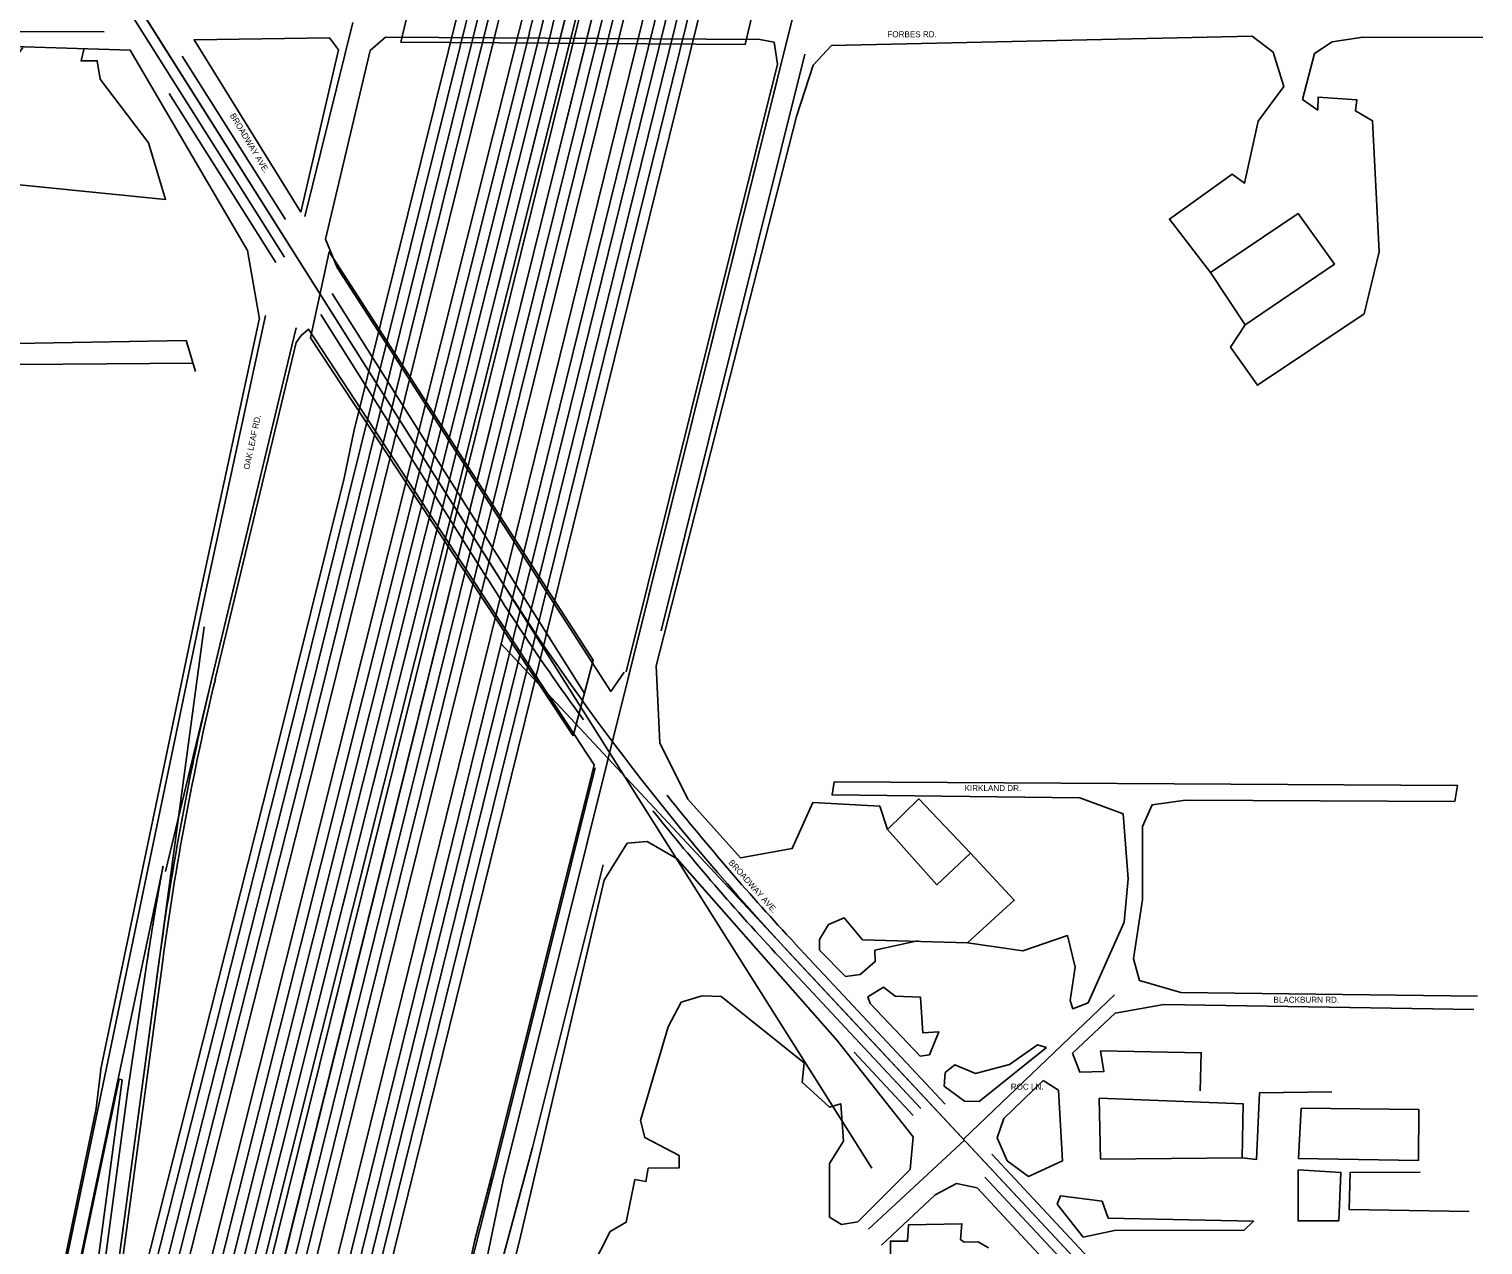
# Model space of a CAD drawing. Extents: x 227157 to 233208, y 434992 to 456232.
# Drawn here: x 228028 to 229709, y 444181 to 445587 of the extents above; entities that cross this region are included whole.
import ezdxf

# ---------------------------------------------------------------- set-up
doc = ezdxf.new("R2010")
doc.units = 0
for name, color, linetype in [('BD_X_Building', 7, 'Continuous'), ('BR_X_Slab_Object', 7, 'Continuous'), ('Default', 7, 'Continuous'), ('GE_X_Alignment', 7, 'Continuous'), ('PM_X_Edge_Line', 7, 'Continuous'), ('PM_X_Lane_Line', 7, 'Continuous'), ('PV_X_EOP', 7, 'Continuous'), ('SV_X_Text_Name', 7, 'Continuous')]:
    doc.layers.add(name, color=color, linetype=linetype)

msp = doc.modelspace()

# ---------------------------------------------------------------- linework, layer by layer
at = {"layer": 'BD_X_Building'}
for points in [[(229394.3, 445305.7), (229434.3, 445245), (229537.4, 445315.1), (229495.4, 445373.8)], [(229020.7, 444661.4), (229057, 444696.9), (229116.6, 444634), (229077.9, 444597.6)], [(229265.6, 444350.8), (229267, 444280.4), (229430.9, 444281.9), (229431.8, 444344.4)], [(229498.9, 444339.5), (229495.8, 444281.3), (229634.6, 444278.9), (229635.2, 444337.7)], [(229495.7, 444268.2), (229495.5, 444208.9), (229542.5, 444209.2), (229544.9, 444265)]]:
    msp.add_lwpolyline(points, close=True, dxfattribs=at)
at = {"layer": 'BR_X_Slab_Object'}
for points in [[(228457.7, 445571.8), (228470.5, 445625.7), (228868.7, 445623.1), (228856.1, 445569.3)], [(228657.1, 444769.9), (228680.1, 444857.3), (228375, 445329.6), (228353.3, 445229.9)]]:
    msp.add_lwpolyline(points, close=True, dxfattribs=at)
at = {"layer": 'Default'}
msp.add_open_spline([(228182.9, 444619.3), (228182.6, 444617.6), (228181.9, 444614), (228180.9, 444608.7), (228180, 444603.3), (228179, 444598), (228178.1, 444592.7), (228177.2, 444587.3), (228176.2, 444582), (228175.3, 444576.6), (228174.4, 444571.3), (228173.5, 444565.9), (228172.6, 444560.6), (228171.7, 444555.2), (228170.9, 444549.8), (228170, 444544.5), (228169.2, 444539.1), (228168.3, 444533.8), (228167.5, 444528.4), (228166.6, 444523), (228165.8, 444517.7), (228165.3, 444514.1), (228165, 444512.3)], degree=3, dxfattribs=at)
at = {"layer": 'GE_X_Alignment'}
for p, q in [((228062.6, 442805), (229317.7, 447888.8)), ((228348.7, 444751.1), (228850.5, 446773.2)), ((227958.1, 442696), (228945.6, 446675.5)), ((227973.9, 442912.3), (228887.3, 446553.8)), ((227769.3, 446224), (229002.6, 444269.9)), ((228576.1, 444256.1), (229057.6, 446188.4)), ((228185.7, 444612.8), (228336.9, 445241.5)), ((227788.2, 442806.3), (228231.6, 444933.5)), ((228012.9, 443278.3), (228230.3, 444895.8)), ((228573.2, 444877), (229685.5, 443685.5)), ((227857.2, 442809.2), (228348.7, 444751.1))]:
    msp.add_line(p, q, dxfattribs=at)
for centre, radius, start, end in [((216725.3, 448562.4), 12285.2, 345.91876, 353.32977), ((231051.2, 446525.5), 2936.3, 212.2571, 223.0314), ((231389.3, 444078.9), 3239.6, 166.4801, 172.3433)]:
    msp.add_arc(centre, radius, start, end, dxfattribs=at)
at = {"layer": 'PM_X_Edge_Line'}
for p, q in [((228568.1, 444958.3), (227769.3, 446224)), ((228361.2, 444014.4), (228765.4, 445651.6)), ((228294, 444049.5), (228690.2, 445646.1)), ((228317.3, 444043.7), (228713.5, 445640.3)), ((228325.4, 444756.9), (228546.3, 445647.1)), ((228348.7, 444751.1), (228569.6, 445641.3)), ((228396.1, 444005.7), (228800.3, 445643)), ((228576.1, 444256.1), (228913.2, 445609)), ((228606.5, 445582.2), (228232.4, 444091)), ((228346.9, 445370.3), (228402.2, 445594.6)), ((228267.3, 444082.3), (228641.4, 445573.4)), ((228759.1, 444891.3), (228925.2, 445558)), ((228313.3, 445317.1), (228189.9, 445512.6)), ((228231.6, 444933.5), (228301.4, 445255.9)), ((228239.4, 444836.2), (228336.9, 445241.5)), ((228030.5, 443969), (228231.6, 444933.5)), ((228163.7, 444117.8), (228325.4, 444756.9)), ((228186.9, 444111.9), (228348.7, 444751.1)), ((228571.1, 444285.9), (228682.5, 444733)), ((228131.1, 444373.2), (228182.9, 444619.3)), ((228610.2, 444294), (228691.7, 444620.8)), ((229685.5, 443685.5), (228904.8, 444521.7)), ((228067, 443681.1), (228178.5, 444510.5)), ((228165, 444512.3), (228141.8, 444357.4)), ((229108.4, 444303.6), (229283, 444470.3)), ((228982, 444403.9), (229050.4, 444330.7)), ((228045.6, 443965.8), (228131.1, 444373.2)), ((228141.8, 444357.4), (228051.2, 443683.3)), ((228542, 444170.2), (228571.1, 444285.9)), ((228571.7, 444150), (228610.2, 444294)), ((228998.7, 444199.4), (229109.7, 444302.3)), ((228555.4, 444155.9), (228576.1, 444256.1))]:
    msp.add_line(p, q, dxfattribs=at)
for centre, radius, start, end in [((216725.3, 448562.4), 12249.2, 345.91876, 353.32977), ((216725.3, 448562.4), 12285.2, 345.91876, 353.32977), ((231051.2, 446525.5), 2936.3, 212.2571, 223.0314), ((231389.3, 444078.9), 3239.6, 166.4801, 172.3433)]:
    msp.add_arc(centre, radius, start, end, dxfattribs=at)
at = {"layer": 'PM_X_Lane_Line'}
for p, q in [((228323.4, 445323.5), (228028.9, 445790.1)), ((228372.8, 444011.5), (228777, 445648.7)), ((228701.8, 445643.2), (228305.7, 444046.6)), ((228337.1, 444754), (228558, 445644.2)), ((228384.5, 444008.6), (228788.7, 445645.9)), ((227924.7, 445584.6), (228114.7, 445583.8)), ((228244.1, 444088.1), (228618.1, 445579.3)), ((228629.7, 445576.4), (228255.7, 444085.2)), ((228205.1, 445555.9), (228324.6, 445366.7)), ((228378.5, 445281.3), (228669.9, 444819.4)), ((228365.4, 445257.1), (228557.9, 444951.9)), ((228175.3, 444114.9), (228337.1, 444754)), ((228913.6, 444529.9), (229087.4, 444343.8)), ((229059.1, 444338.9), (228896.1, 444513.5)), ((229141.3, 444286.1), (229528.4, 443871.4)), ((229505.7, 443860.5), (229133.3, 444259.5))]:
    msp.add_line(p, q, dxfattribs=at)
for centre, radius, start, end in [((216725.3, 448562.4), 12261.2, 345.91876, 353.32977), ((216725.3, 448562.4), 12273.2, 345.91876, 353.32977), ((231051.2, 446525.5), 2948.3, 212.2571, 216.1028), ((231051.2, 446525.5), 2924.3, 218.6008, 223.0314), ((231051.2, 446525.5), 2948.3, 218.6722, 223.0314)]:
    msp.add_arc(centre, radius, start, end, dxfattribs=at)
at = {"layer": 'PV_X_EOP'}
for p, q in [((228280.4, 444052.9), (228676.6, 445649.5)), ((228347.6, 444017.7), (228751.8, 445655)), ((228403.6, 445121.9), (228534.7, 445650)), ((228328.9, 444040.8), (228725.1, 445637.4)), ((228360.3, 444748.2), (228581.3, 445638.4)), ((228407.8, 444002.9), (228812, 445640.1)), ((228220.8, 444093.9), (228594.8, 445585.1)), ((228279, 444079.3), (228653, 445570.5)), ((228422.6, 445562.3), (228370.7, 445344.3)), ((228718.4, 444843.9), (228893.5, 445546.6)), ((228225.7, 444934.7), (228294.2, 445251.3)), ((228336.9, 445224.6), (228342.5, 445232.7)), ((228209.5, 445227.1), (228220.5, 445191.3)), ((228336.9, 445224.6), (228243.3, 444835.3)), ((228392.2, 445067.6), (228403.6, 445121.9)), ((228315.7, 444759.4), (228392.2, 445067.6)), ((228110.7, 444382.9), (228225.7, 444934.7)), ((228154, 444120.3), (228315.7, 444759.4)), ((228198.6, 444109), (228360.3, 444748.2)), ((228562.4, 444259.2), (228681.3, 444736.4)), ((228942, 444522.2), (228972, 444491.4)), ((228182.5, 444510), (228106.7, 443946.3)), ((229000.8, 444460.3), (229058.4, 444399.3)), ((228043.2, 443684.3), (228135.7, 444371.9)), ((228046.6, 443965.6), (228132.1, 444372.9)), ((228105.6, 444338.8), (228111, 444383.5)), ((228131.1, 444373.2), (228135.7, 444371.9)), ((228028.6, 443969.4), (228105.6, 444338.8)), ((228543, 444185), (228562.4, 444259.2)), ((228562.3, 444258.8), (228562.4, 444259.2)), ((229510.8, 443831.9), (229124.3, 444247.2)), ((229216.7, 444228.5), (229247, 444190.3)), ((229554.7, 444222.1), (229693.2, 444219.9)), ((228537.8, 444159.9), (228543, 444185))]:
    msp.add_line(p, q, dxfattribs=at)
for points in [[(227744.7, 445578), (227773.6, 445563), (227776.7, 445488.4), (227778.9, 445253.6), (227812.4, 445212.5), (227864.9, 445197.9), (228218.3, 445200.8)], [(228209.5, 445227.1), (227880.9, 445221.1), (227825.6, 445227.3), (227807.4, 445252.2), (227803.5, 445561.5), (227826.5, 445572.7)], [(228294.6, 445251.8), (228280.4, 445330.9), (228145, 445562.5), (227826.5, 445572.7)], [(228020.6, 445565.8), (228016, 445559.1), (227956.5, 445549.2), (227959.2, 445412.9), (228185.9, 445390.2), (228166.1, 445455.4), (228110.2, 445529), (228106.9, 445550.5), (228088.1, 445550.2), (228091.1, 445563.5)], [(228422.6, 445562.3), (228440.1, 445577.6), (228872.9, 445575.2), (228889.5, 445571.9), (228893.5, 445546.6)], [(228753, 444850.8), (228915.4, 445485.9), (228934.8, 445545.3), (228956, 445568)], [(228956, 445568), (229442.3, 445578.8), (229466.6, 445560.2)], [(229514.4, 445558.9), (229534.9, 445572.4), (229570.2, 445577.9), (229709.2, 445577.3)], [(229466.6, 445560.2), (229478.8, 445520.7), (229449.4, 445480.7), (229433.4, 445408.9), (229419.2, 445419.2), (229346.7, 445367.3), (229394.3, 445305.7)], [(229434.3, 445245), (229417.4, 445219.1), (229448.5, 445175.3), (229571.8, 445257.9), (229589.2, 445329.5), (229581.7, 445481), (229561.8, 445492.5), (229563.4, 445505.3), (229518.6, 445508.5), (229518.2, 445493.5), (229500.5, 445505.6), (229514.4, 445558.9)], [(228370.7, 445344.3), (228384.2, 445311.4), (228700.6, 444821.2), (228716.3, 444843.5)], [(228681.3, 444736.4), (228351.2, 445239.9), (228342.5, 445232.7)], [(228850.5, 444628.6), (228789.6, 444696.5), (228757.2, 444761.8), (228753, 444850.8)], [(229252.9, 444461.1), (229294.5, 444554.5), (229299.1, 444604.6), (229293.3, 444679.5), (229243.2, 444698.3), (228956.6, 444701.6), (228958.9, 444716.6), (229679.7, 444712.6), (229676.7, 444694), (229365.1, 444695.5), (229326.7, 444690.1), (229315.5, 444665.2)], [(228850.5, 444628.6), (228910.5, 444639.4), (228934.4, 444692.8), (229011.7, 444688.4), (229020.7, 444661.4)], [(229315.5, 444665.2), (229315.5, 444580.6), (229305.1, 444511.9), (229311.9, 444486.8), (229359.9, 444473.1), (229702.8, 444468.9)], [(228719.6, 444645.6), (228693, 444602.8), (228594.8, 444184.3), (228521.3, 443893.9), (228494.9, 443739.1), (228462.9, 443544.8), (228445.5, 443382.8)], [(229050.4, 444306.3), (228962.4, 444417.5), (228777.6, 444627.7), (228742.6, 444647.5), (228719.6, 444645.6)], [(229116.6, 444634), (229167.2, 444579.8), (229113.3, 444530.6), (229177.2, 444521.4), (229228.7, 444538.9), (229237.5, 444502.3), (229231.8, 444463.9), (229234.8, 444454.2), (229252.9, 444461.1)], [(229113.3, 444530.6), (228991.9, 444534.1), (228970.4, 444559.4), (228952.3, 444551.7), (228942, 444534.5), (228942, 444522.2)], [(228972, 444491.4), (228988.9, 444493.9), (229006.4, 444508.9), (229006.1, 444522), (229055.5, 444532.7)], [(229058.4, 444399.3), (229069.1, 444400.9), (229080.1, 444427.5), (229061.6, 444426.4), (229058.9, 444467.5), (229029.6, 444468.8), (229016, 444479.2), (228998, 444467.9), (229000.8, 444460.3)], [(228953.4, 444213.1), (228953.7, 444275.3), (228969.9, 444301.3), (228966.6, 444344.5), (228953.4, 444340.5), (228921.9, 444369.2), (228924.3, 444391.9), (228828.4, 444468.3), (228806.3, 444469.2), (228782.1, 444461.7), (228767.2, 444433.5), (228734.9, 444324.9), (228739.9, 444305.3), (228779.9, 444284.5), (228779.6, 444270.2), (228743.8, 444269.9), (228741.2, 444254.4), (228728.5, 444256.7), (228718.5, 444207.4), (228699.8, 444196.6), (228668.1, 444133.8)], [(229698.8, 444453.3), (229340.1, 444459), (229283.8, 444449.2), (229234.7, 444402.9)], [(229204.6, 444409.4), (229194.2, 444412.7), (229161.9, 444389.7), (229122.3, 444379.5), (229098.5, 444389.4), (229087.3, 444380.4), (229086.1, 444364.6)], [(229086.1, 444364.6), (229109.6, 444347.4), (229126.7, 444346.9), (229204.6, 444409.4)], [(229234.7, 444402.9), (229243.1, 444380.8), (229271, 444381.6), (229267.1, 444405.5), (229383.4, 444403.4), (229382.4, 444359.2)], [(229200.5, 444371.5), (229155.2, 444327.4), (229147.5, 444305.1), (229159, 444278.5), (229183.8, 444260.3)], [(229200.5, 444371.5), (229218.5, 444360), (229223.1, 444278.3), (229183.8, 444260.3)], [(229430.9, 444281.9), (229447.4, 444280), (229450.8, 444357), (229534.6, 444358.1)], [(228953.4, 444213.1), (228967.6, 444204.9), (228986.2, 444207.8), (229046.7, 444268.3), (229050.4, 444306.3)], [(229124.3, 444247.2), (229100.4, 444252.2), (229075.8, 444239.3), (229013.7, 444181)], [(229554.7, 444222.1), (229555.6, 444265), (229636.5, 444265.5)], [(229216.7, 444228.5), (229220.6, 444238), (229268.8, 444231.7), (229275.9, 444212.3), (229444, 444208.6), (229433, 444198.4), (229283.1, 444197.9), (229247, 444190.3)], [(229023.6, 444131.2), (229024.1, 444185.6), (229043.7, 444185.6), (229044.8, 444204.4), (229106.8, 444205.7), (229105.2, 444187.4), (229109.2, 444184.3), (229125.5, 444184.8), (229137.4, 444177.8)]]:
    msp.add_lwpolyline(points, dxfattribs=at)
msp.add_lwpolyline([(228342.2, 445375.4), (228218.8, 445574.7), (228375.5, 445576.9), (228385.9, 445563.2)], close=True, dxfattribs=at)
for centre, radius, start, end in [((216725.3, 448562.4), 12237.2, 345.91876, 353.32977), ((216725.3, 448562.4), 12297.2, 345.91876, 353.32977), ((231389.3, 444078.9), 3235.6, 166.4801, 172.3433)]:
    msp.add_arc(centre, radius, start, end, dxfattribs=at)

# ---------------------------------------------------------------- texts
at = {"layer": 'SV_X_Text_Name'}
for s, p in [('FORBES RD.', (229020.5, 445577.6)), ('KIRKLAND DR.', (229109.8, 444705.9)), ('BLACKBURN RD.', (229467, 444461.2)), ('ROC LN.', (229163.2, 444360.6))]:
    msp.add_text(s, height=7, dxfattribs=at).set_placement(p)
for s, rotation, p in [('BROADWAY AVE.', 300.9149, (228259.8, 445487.2)), ('OAK LEAF RD.', 77.9251, (228282.6, 445077.2)), ('BROADWAY AVE.', 311.7911, (228836.3, 444622.9))]:
    msp.add_text(s, height=7, rotation=rotation, dxfattribs=at).set_placement(p)

doc.saveas('drawing.dxf')
